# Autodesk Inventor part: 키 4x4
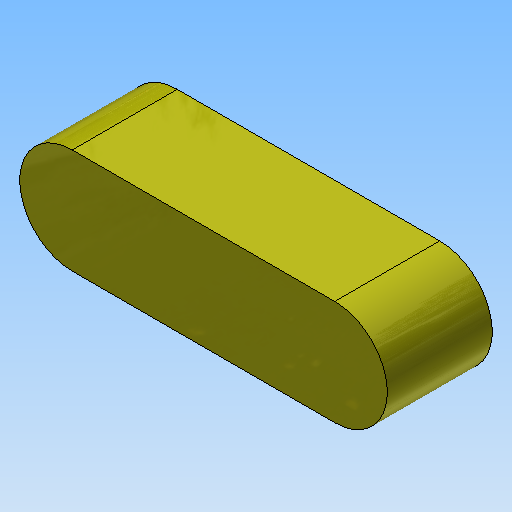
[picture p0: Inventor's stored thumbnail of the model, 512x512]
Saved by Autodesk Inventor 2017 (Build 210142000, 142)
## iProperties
Created: 2018-09
Part Number: 키 4x4
Document SubType Name: Modeling
Density: 1 g/cm^3
Material: 강철, 연강
Appearance: 노란색
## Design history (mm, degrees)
sketch "스케치1"
  geometry: L1 (-5, -2)-(5, -2); L2 (5, 2)-(-5, 2); A1 r 2 centre (5, 0) between (5, -2) and (5, 2); A2 r 2 centre (-5, 0) between (-5, 2) and (-5, -2); 2 further points
  constraints: 4 end point, 4 point on circle, 4 tangent, 2 centre point, 1 horizontal, 1 horizontal alignment, 1 midpoint, 1 parallel, 1 vertical alignment
  dimensions: "d0" = 4 distance between parallel lines of L1 L2; "d1" = 14 dimension on A1 A2
extrude "돌출1" new body sketch "스케치1" stored distance "d2" = 4; taper "d3" = 0 deg
node "솔리드1"
